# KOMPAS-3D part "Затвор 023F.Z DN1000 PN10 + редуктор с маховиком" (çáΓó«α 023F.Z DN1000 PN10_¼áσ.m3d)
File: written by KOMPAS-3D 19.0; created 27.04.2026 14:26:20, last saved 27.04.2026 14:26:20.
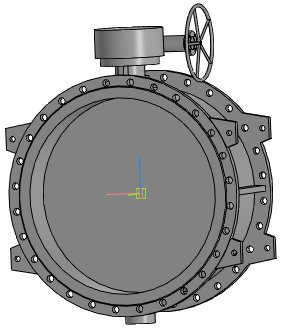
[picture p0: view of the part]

Document properties: Полное имя файла: ..\..\Затвор 023F.Z DN200-DN1600_с маховиком\Затвор 023F.Z DN1000 PN10 + редуктор с маховиком.a3d

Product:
- Part/product: Затвор 023F.Z DN1000 PN10 + редуктор с маховиком
    Масса: 1316.86

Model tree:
1. Операция без истории:1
